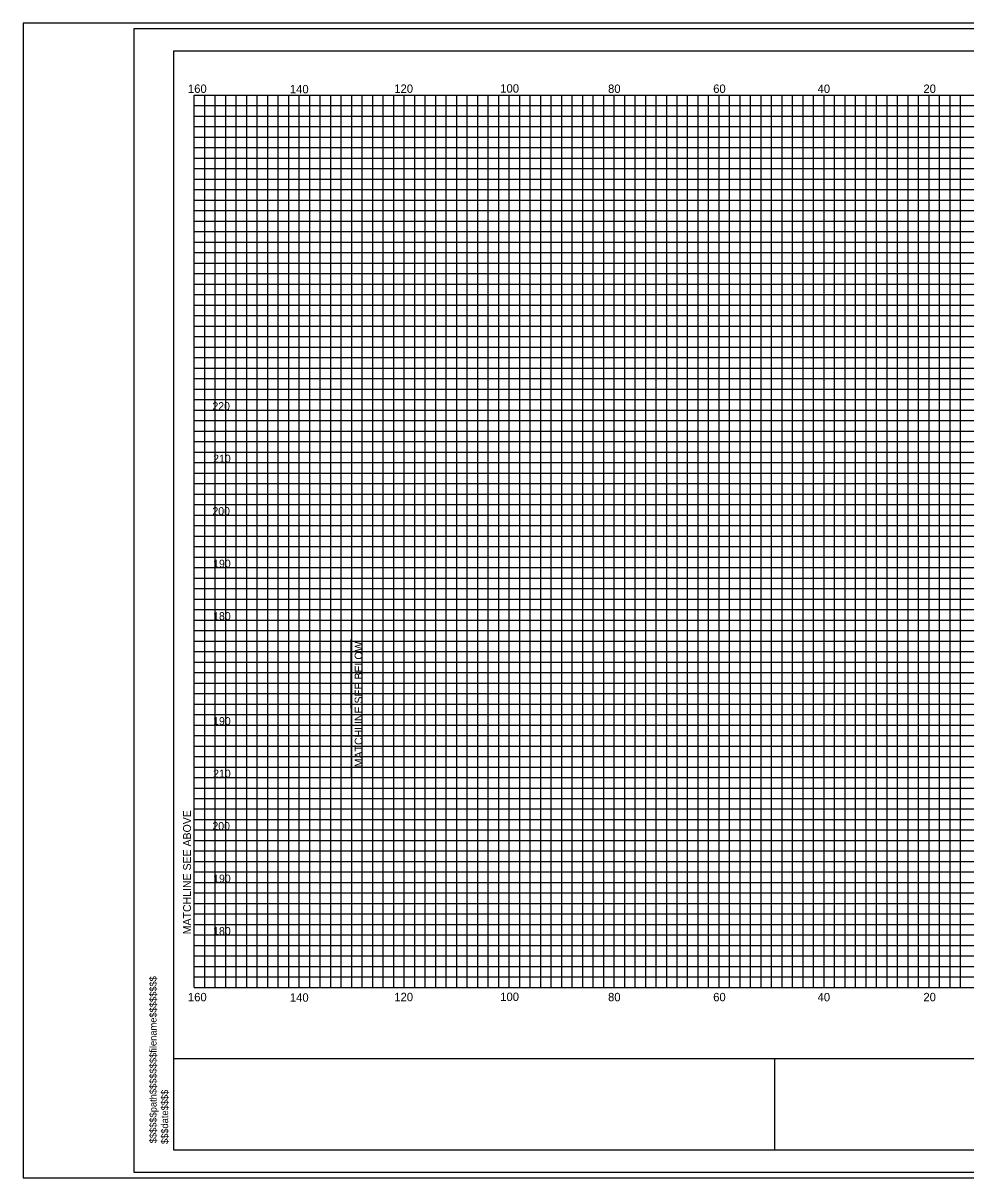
# Model space of a CAD drawing. Extents: x 967 to 1326, y 964 to 2584.
# Drawn here: x 967.4 to 1147, y 2083.7 to 2303.7 of the extents above; entities that cross this region are included whole.
import ezdxf

# ---------------------------------------------------------------- set-up
doc = ezdxf.new("R2010")
doc.units = 0
for name, color, linetype in [('Default', 7, 'Continuous'), ('RD_SHT_Bndy', 7, 'Continuous'), ('RD_SHT_IplotShp', 7, 'Continuous'), ('RD_SHT_MjGrid', 7, 'Continuous'), ('RD_SHT_MnGrid', 7, 'Continuous'), ('RD_SHT_TX', 7, 'Continuous'), ('RD_Sketch1', 7, 'Continuous'), ('RD_XS_TX_Station', 7, 'Continuous')]:
    doc.layers.add(name, color=color, linetype=linetype)

msp = doc.modelspace()

# ---------------------------------------------------------------- linework, layer by layer
at = {"layer": 'RD_SHT_Bndy'}
for p, q in [((996.11, 2088.98), (996.11, 2298.46)), ((996.11, 2298.46), (1323.89, 2298.46)), ((996.11, 2106.49), (1323.89, 2106.49)), ((1110.59, 2088.98), (1110.59, 2106.56)), ((1323.89, 2088.98), (996.11, 2088.98))]:
    msp.add_line(p, q, dxfattribs=at)
at = {"layer": 'RD_SHT_IplotShp'}
for points in [[(967.41, 2083.72), (1326.28, 2083.72), (1326.28, 2303.72), (967.41, 2303.72)], [(988.52, 2084.84), (1326.28, 2084.84), (1326.28, 2302.6), (988.52, 2302.6)]]:
    msp.add_lwpolyline(points, close=True, dxfattribs=at)
at = {"layer": 'RD_SHT_MjGrid'}
for p, q in [((1000, 2290), (1320, 2290)), ((1000, 2120), (1000, 2290)), ((1010, 2120), (1010, 2290)), ((1020, 2120), (1020, 2290)), ((1030, 2120), (1030, 2290)), ((1040, 2120), (1040, 2290)), ((1050, 2120), (1050, 2290)), ((1060, 2120), (1060, 2290)), ((1070, 2120), (1070, 2290)), ((1080, 2120), (1080, 2290)), ((1090, 2120), (1090, 2290)), ((1100, 2120), (1100, 2290)), ((1110, 2120), (1110, 2290)), ((1120, 2120), (1120, 2290)), ((1130, 2120), (1130, 2290)), ((1140, 2120), (1140, 2290)), ((1000, 2280), (1320, 2280)), ((1000, 2270), (1320, 2270)), ((1000, 2260), (1320, 2260)), ((1000, 2250), (1320, 2250)), ((1000, 2240), (1320, 2240)), ((1000, 2230), (1320, 2230)), ((1000, 2220), (1320, 2220)), ((1000, 2210), (1320, 2210)), ((1000, 2200), (1320, 2200)), ((1000, 2190), (1320, 2190)), ((1000, 2180), (1320, 2180)), ((1000, 2170), (1320, 2170)), ((1000, 2160), (1320, 2160)), ((1000, 2150), (1320, 2150)), ((1000, 2140), (1320, 2140)), ((1000, 2130), (1320, 2130)), ((1000, 2120), (1320, 2120))]:
    msp.add_line(p, q, dxfattribs=at)
at = {"layer": 'RD_SHT_MnGrid'}
for p, q in [((1000, 2288), (1320, 2288)), ((1002, 2120), (1002, 2290)), ((1004, 2120), (1004, 2290)), ((1006, 2120), (1006, 2290)), ((1008, 2120), (1008, 2290)), ((1012, 2120), (1012, 2290)), ((1014, 2120), (1014, 2290)), ((1016, 2120), (1016, 2290)), ((1018, 2120), (1018, 2290)), ((1022, 2120), (1022, 2290)), ((1024, 2120), (1024, 2290)), ((1026, 2120), (1026, 2290)), ((1028, 2120), (1028, 2290)), ((1032, 2120), (1032, 2290)), ((1034, 2120), (1034, 2290)), ((1036, 2120), (1036, 2290)), ((1038, 2120), (1038, 2290)), ((1042, 2120), (1042, 2290)), ((1044, 2120), (1044, 2290)), ((1046, 2120), (1046, 2290)), ((1048, 2120), (1048, 2290)), ((1052, 2120), (1052, 2290)), ((1054, 2120), (1054, 2290)), ((1056, 2120), (1056, 2290)), ((1058, 2120), (1058, 2290)), ((1062, 2120), (1062, 2290)), ((1064, 2120), (1064, 2290)), ((1066, 2120), (1066, 2290)), ((1068, 2120), (1068, 2290)), ((1072, 2120), (1072, 2290)), ((1074, 2120), (1074, 2290)), ((1076, 2120), (1076, 2290)), ((1078, 2120), (1078, 2290)), ((1082, 2120), (1082, 2290)), ((1084, 2120), (1084, 2290)), ((1086, 2120), (1086, 2290)), ((1088, 2120), (1088, 2290)), ((1092, 2120), (1092, 2290)), ((1094, 2120), (1094, 2290)), ((1096, 2120), (1096, 2290)), ((1098, 2120), (1098, 2290)), ((1102, 2120), (1102, 2290)), ((1104, 2120), (1104, 2290)), ((1106, 2120), (1106, 2290)), ((1108, 2120), (1108, 2290)), ((1112, 2120), (1112, 2290)), ((1114, 2120), (1114, 2290)), ((1116, 2120), (1116, 2290)), ((1118, 2120), (1118, 2290)), ((1122, 2120), (1122, 2290)), ((1124, 2120), (1124, 2290)), ((1126, 2120), (1126, 2290)), ((1128, 2120), (1128, 2290)), ((1132, 2120), (1132, 2290)), ((1134, 2120), (1134, 2290)), ((1136, 2120), (1136, 2290)), ((1138, 2120), (1138, 2290)), ((1142, 2120), (1142, 2290)), ((1144, 2120), (1144, 2290)), ((1146, 2120), (1146, 2290)), ((1000, 2286), (1320, 2286)), ((1000, 2284), (1320, 2284)), ((1000, 2282), (1320, 2282)), ((1000, 2278), (1320, 2278)), ((1000, 2276), (1320, 2276)), ((1000, 2274), (1320, 2274)), ((1000, 2272), (1320, 2272)), ((1000, 2268), (1320, 2268)), ((1000, 2266), (1320, 2266)), ((1000, 2264), (1320, 2264)), ((1000, 2262), (1320, 2262)), ((1000, 2258), (1320, 2258)), ((1000, 2256), (1320, 2256)), ((1000, 2254), (1320, 2254)), ((1000, 2252), (1320, 2252)), ((1000, 2248), (1320, 2248)), ((1000, 2246), (1320, 2246)), ((1000, 2244), (1320, 2244)), ((1000, 2242), (1320, 2242)), ((1000, 2238), (1320, 2238)), ((1000, 2236), (1320, 2236)), ((1000, 2234), (1320, 2234)), ((1000, 2232), (1320, 2232)), ((1000, 2228), (1320, 2228)), ((1000, 2226), (1320, 2226)), ((1000, 2224), (1320, 2224)), ((1000, 2222), (1320, 2222)), ((1000, 2218), (1320, 2218)), ((1000, 2216), (1320, 2216)), ((1000, 2214), (1320, 2214)), ((1000, 2212), (1320, 2212)), ((1000, 2208), (1320, 2208)), ((1000, 2206), (1320, 2206)), ((1000, 2204), (1320, 2204)), ((1000, 2202), (1320, 2202)), ((1000, 2198), (1320, 2198)), ((1000, 2196), (1320, 2196)), ((1000, 2194), (1320, 2194)), ((1000, 2192), (1320, 2192)), ((1000, 2188), (1320, 2188)), ((1000, 2186), (1320, 2186)), ((1000, 2184), (1320, 2184)), ((1000, 2182), (1320, 2182)), ((1000, 2178), (1320, 2178)), ((1000, 2176), (1320, 2176)), ((1000, 2174), (1320, 2174)), ((1000, 2172), (1320, 2172)), ((1000, 2168), (1320, 2168)), ((1000, 2166), (1320, 2166)), ((1000, 2164), (1320, 2164)), ((1000, 2162), (1320, 2162)), ((1000, 2158), (1320, 2158)), ((1000, 2156), (1320, 2156)), ((1000, 2154), (1320, 2154)), ((1000, 2152), (1320, 2152)), ((1000, 2148), (1320, 2148)), ((1000, 2146), (1320, 2146)), ((1000, 2144), (1320, 2144)), ((1000, 2142), (1320, 2142)), ((1000, 2138), (1320, 2138)), ((1000, 2136), (1320, 2136)), ((1000, 2134), (1320, 2134)), ((1000, 2132), (1320, 2132)), ((1000, 2128), (1320, 2128)), ((1000, 2126), (1320, 2126)), ((1000, 2124), (1320, 2124)), ((1000, 2122), (1320, 2122))]:
    msp.add_line(p, q, dxfattribs=at)
at = {"layer": 'RD_Sketch1'}
msp.add_lwpolyline([(967.41, 2083.72), (1326.28, 2083.72), (1326.28, 2303.72), (967.41, 2303.72)], close=True, dxfattribs=at)
at = {"layer": 'RD_XS_TX_Station'}
msp.add_line((1029.96, 2160), (1029.93, 2186.28), dxfattribs=at)

# ---------------------------------------------------------------- texts
at = {"layer": 'Default'}
for s, p in [('220', (1003.47, 2230)), ('210', (1003.61, 2220)), ('200', (1003.47, 2210)), ('190', (1003.61, 2200)), ('180', (1003.61, 2190)), ('190', (1003.61, 2170)), ('210', (1003.61, 2160)), ('200', (1003.47, 2150)), ('190', (1003.61, 2140)), ('180', (1003.61, 2130))]:
    msp.add_text(s, height=1.5, dxfattribs=at).set_placement(p)
for s, p in [('$$$$$$path$$$$$$$$filename$$$$$$$$', (992.83, 2090.31)), ('$$$date$$$$', (995.04, 2090.17))]:
    msp.add_text(s, height=1.3258, rotation=90, dxfattribs=at).set_placement(p)
at = {"layer": 'RD_SHT_TX'}
for s, p in [('160', (998.81, 2290.42)), ('140', (1018.23, 2290.34)), ('120', (1038.12, 2290.43)), ('100', (1058.3, 2290.47)), ('80', (1078.84, 2290.42)), ('60', (1098.86, 2290.42)), ('40', (1118.75, 2290.41)), ('20', (1138.91, 2290.42)), ('160', (998.81, 2117.37)), ('140', (1018.23, 2117.29)), ('120', (1038.12, 2117.38)), ('100', (1058.3, 2117.42)), ('80', (1078.84, 2117.37)), ('60', (1098.86, 2117.37)), ('40', (1118.75, 2117.36)), ('20', (1138.91, 2117.37))]:
    msp.add_text(s, height=1.6, dxfattribs=at).set_placement(p)
at = {"layer": 'RD_XS_TX_Station'}
for s, p in [('MATCHLINE SEE BELOW', (1032.07, 2161.95)), ('MATCHLINE SEE ABOVE', (999.39, 2130.14))]:
    msp.add_text(s, height=1.5, rotation=90, dxfattribs=at).set_placement(p)

doc.saveas('drawing.dxf')
